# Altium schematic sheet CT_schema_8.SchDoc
size 226 x 144 mm
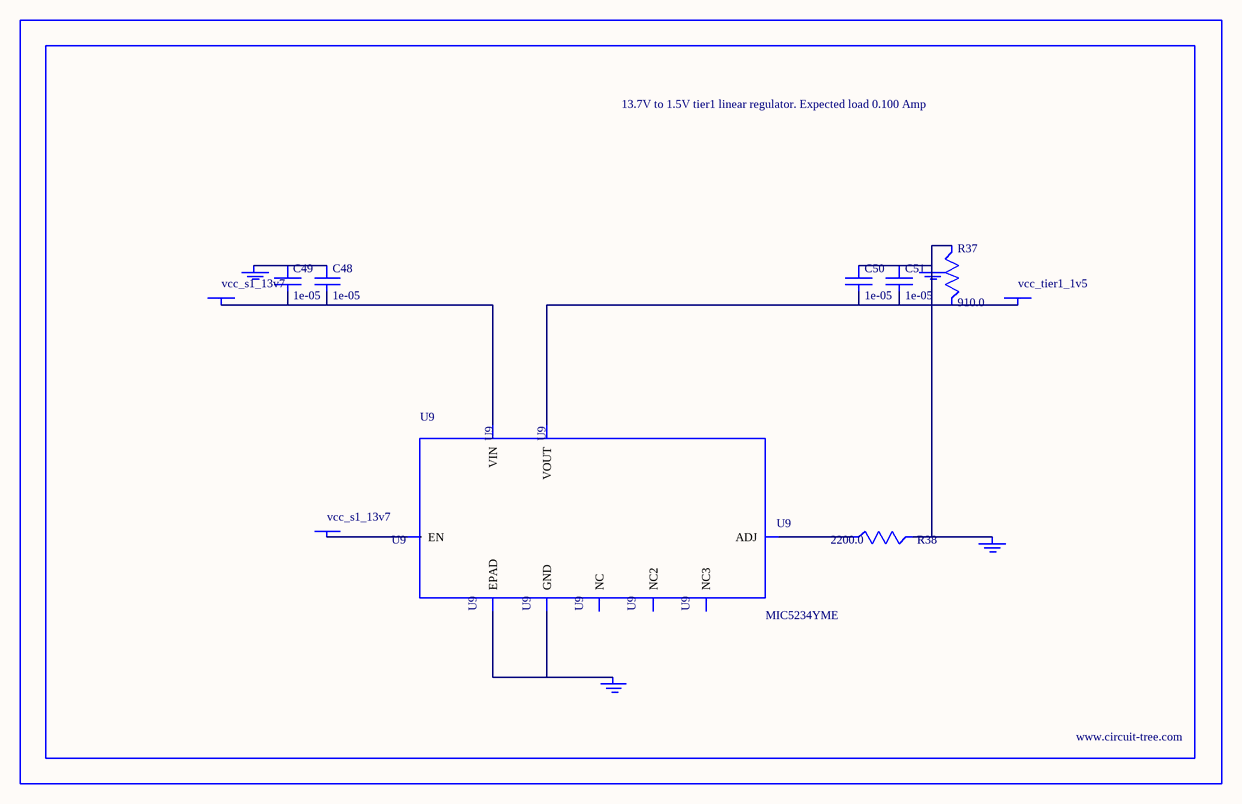
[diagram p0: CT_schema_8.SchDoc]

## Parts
BORDER7  (no value)
C48  1e-05  [C1210]
C49  1e-05  [C1210]
C50  1e-05  [C1210]
C51  1e-05  [C1210]
GND_INSTANCE_7_0  (no value)
GND_INSTANCE_7_1  (no value)
GND_INSTANCE_7_2  (no value)
GND_INSTANCE_7_3  (no value)
POWER_INSTANCE_7_0  vcc_tier1_1v5
POWER_INSTANCE_7_1  vcc_s1_13v7
POWER_INSTANCE_7_2  vcc_s1_13v7
R37  910.0  [R0603]
R38  2200.0  [R0603]
U9  MIC5234YME  [SOIC-8_EP]

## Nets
NetC48_1: C48.1 C49.1 GND_INSTANCE_7_3.0(GND)
NetC48_2: C48.2 C49.2 POWER_INSTANCE_7_2.0(PWR) U9.8(VIN)
NetC50_1: C50.1 C51.1 GND_INSTANCE_7_0.0(GND) GND_INSTANCE_7_1.0(GND) R37.1 R38.2
NetC50_2: C50.2 C51.2 POWER_INSTANCE_7_0.0(PWR) R37.2 U9.1(VOUT)
NetGND_INSTANCE_7_2_0: GND_INSTANCE_7_2.0(GND) U9.7(GND) U9.EPAD
NetPOWER_INSTANCE_7_1_0: POWER_INSTANCE_7_1.0(PWR) U9.5(EN)
NetR38_1: R38.1 U9.4(ADJ)

Not connected (* = marked no-connect by the designer): U9 2(NC) 3(NC2) 6(NC3)

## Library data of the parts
BORDER7 = BORDER_PAGE7
C48-C51 = C1210C106K5PACTU
GND_INSTANCE_7_0-GND_INSTANCE_7_3 = GND
POWER_INSTANCE_7_0-POWER_INSTANCE_7_2 = PWR
R37 = RC0603JR-07910RL
R38 = RC0603JR-072K2L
